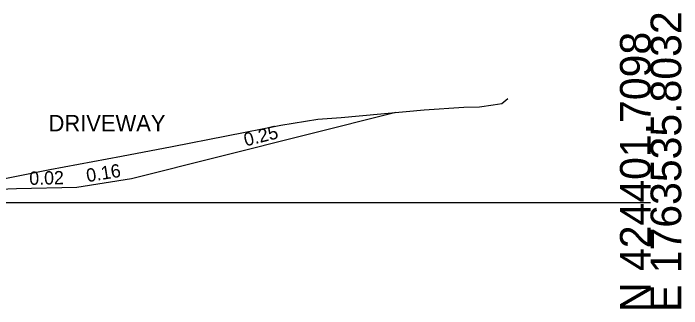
# Model space of a CAD drawing. Extents: x -26 to 3203, y -11010 to 4024.
# Drawn here: x 2141.7 to 2202.8, y -1009.7 to -982.7 of the extents above; entities that cross this region are included whole.
import ezdxf

# ---------------------------------------------------------------- set-up
doc = ezdxf.new("R2010")
doc.units = 0
for name, color, linetype in [('Exist Cross Section Cell', 7, 'Continuous'), ('Exist XS Ground Line', 7, 'Continuous'), ('Prop CMT Conc Surface', 7, 'Continuous'), ('Prop CMT Template Flag', 7, 'Continuous'), ('Prop XS SE Text', 7, 'Continuous'), ('Prop XS Side Slope Text', 7, 'Continuous'), ('Scratch_Level_0', 7, 'Continuous')]:
    doc.layers.add(name, color=color, linetype=linetype)

msp = doc.modelspace()

# ---------------------------------------------------------------- linework, layer by layer
at = {"layer": 'Exist Cross Section Cell'}
msp.add_line((2100, -1000), (2200, -1000), dxfattribs=at)
at = {"layer": 'Exist XS Ground Line'}
msp.add_lwpolyline([(2140.631, -997.871), (2145.037, -996.989), (2151.604, -995.749), (2156.233, -994.868), (2166.182, -992.909), (2169.571, -992.365), (2171.704, -992.208), (2179.288, -991.507), (2182.905, -991.29), (2184.356, -991.233), (2185.599, -991.063), (2186.393, -990.944), (2186.945, -990.488)], dxfattribs=at)
msp.add_lwpolyline([(2140.631, -997.871), (2145.037, -996.989), (2151.604, -995.749), (2156.233, -994.868), (2166.182, -992.909), (2169.571, -992.365), (2171.704, -992.208), (2179.288, -991.507), (2182.905, -991.29), (2184.356, -991.233), (2185.599, -991.063), (2186.393, -990.944), (2186.945, -990.488)], dxfattribs=at)
msp.add_lwpolyline([(2140.631, -997.871), (2145.037, -996.989), (2151.604, -995.749), (2156.233, -994.868), (2166.182, -992.909), (2169.571, -992.365), (2171.704, -992.208), (2179.288, -991.507), (2182.905, -991.29), (2184.356, -991.233), (2185.599, -991.063), (2186.393, -990.944), (2186.945, -990.488)], dxfattribs=at)
msp.add_lwpolyline([(2140.631, -997.871), (2145.037, -996.989), (2151.604, -995.749), (2156.233, -994.868), (2166.182, -992.909), (2169.571, -992.365), (2171.704, -992.208), (2179.288, -991.507), (2182.905, -991.29), (2184.356, -991.233), (2185.599, -991.063), (2186.393, -990.944), (2186.945, -990.488)], dxfattribs=at)
msp.add_lwpolyline([(2140.631, -997.871), (2145.037, -996.989), (2151.604, -995.749), (2156.233, -994.868), (2166.182, -992.909), (2169.571, -992.365), (2171.704, -992.208), (2179.288, -991.507), (2182.905, -991.29), (2184.356, -991.233), (2185.599, -991.063), (2186.393, -990.944), (2186.945, -990.488)], dxfattribs=at)
at = {"layer": 'Prop CMT Conc Surface'}
msp.add_lwpolyline([(2138, -998.866), (2142, -998.706), (2147.501, -998.596)], dxfattribs=at)
at = {"layer": 'Prop CMT Template Flag'}
msp.add_lwpolyline([(2147.501, -998.596), (2152.501, -997.796), (2176.702, -991.746)], dxfattribs=at)

# ---------------------------------------------------------------- texts
at = {"layer": 'Exist Cross Section Cell'}
for s, p in [('E 1763535.8032', (2202.8, -1010)), ('N 424401.7098', (2200, -1010))]:
    msp.add_text(s, height=2.8, rotation=90, dxfattribs=at).set_placement(p)
at = {"layer": 'Prop XS SE Text'}
msp.add_text('DRIVEWAY', height=1.5, rotation=360, dxfattribs=at).set_placement((2144.92, -993.488))
at = {"layer": 'Prop XS Side Slope Text'}
for s, rotation, p in [('0.25', 14.03624, (2162.957, -994.873)), ('0.16', 9.09028, (2148.474, -998.137)), ('0.02', 1.14576, (2143.17, -998.383))]:
    msp.add_text(s, height=1.215, rotation=rotation, dxfattribs=at).set_placement(p)
at = {"layer": 'Scratch_Level_0'}
for s, p in [('Exterior Boundary', (2176.543, -991.756)), ('RT_Slope_Cut', (2176.598, -991.756)), ('RT_SS_Cut_1BrkPnt', (2152.351, -997.806)), ('RT_Berm_A', (2141.917, -998.716)), ('RT_GS_OS_CTL', (2147.394, -998.606))]:
    msp.add_text(s, height=0.02, dxfattribs=at).set_placement(p)

doc.saveas('drawing.dxf')
